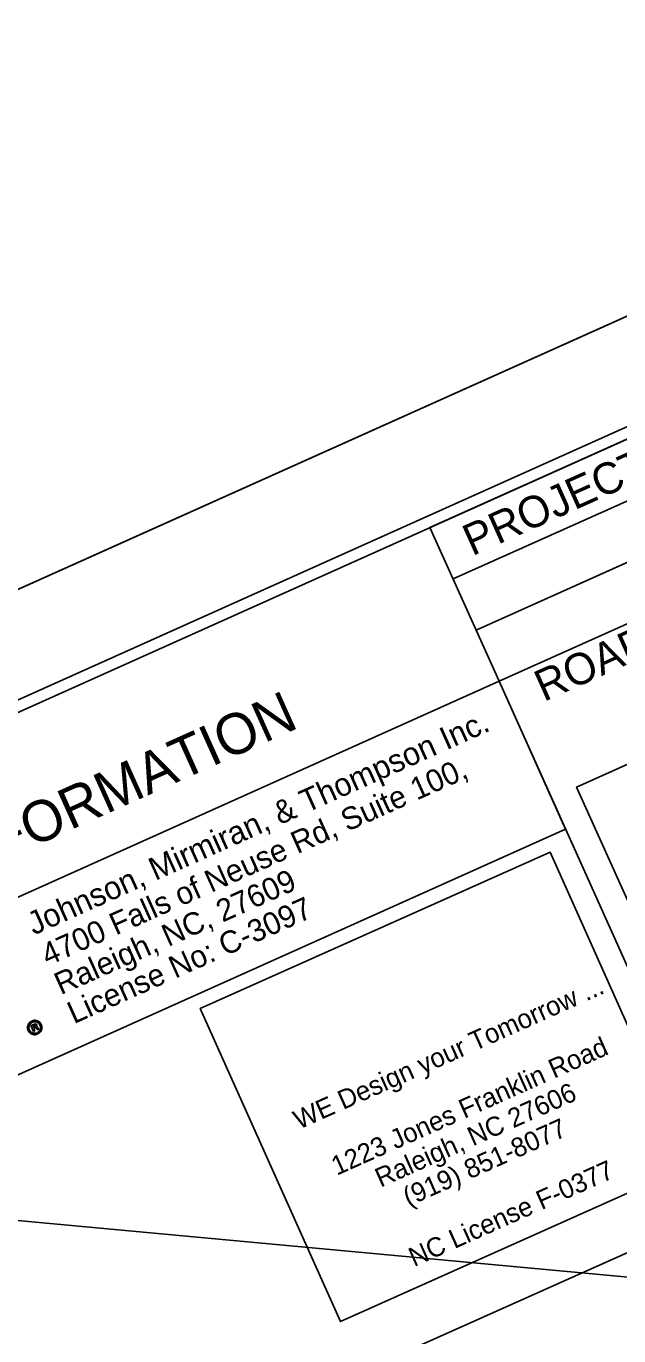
# Model space of a CAD drawing. Extents: x 553939 to 555925, y 502653 to 504347.
# Drawn here: x 555197.2 to 555329.1, y 504054.8 to 504346.6 of the extents above; entities that cross this region are included whole.
import ezdxf

# ---------------------------------------------------------------- set-up
doc = ezdxf.new("R2010")
doc.units = 0
for name, color, linetype in [('Matchline', 7, 'Continuous'), ('Prop DSN Text', 7, 'Continuous'), ('Prop Horizontal Alignment Curve and Spiral Data', 7, 'Continuous'), ('Sheet Border Standard 30in CELL', 7, 'Continuous'), ('Sheet Clip Boundary CELL', 7, 'Continuous'), ('Sheet Cutting Line CELL', 7, 'Continuous'), ('Sheet Plot Border Inside CELL', 7, 'Continuous'), ('Sheet Plot Border Outside CELL', 7, 'Continuous'), ('Sheet Sticker Incomplete CELL', 7, 'Continuous')]:
    doc.layers.add(name, color=color, linetype=linetype)

msp = doc.modelspace()

# ---------------------------------------------------------------- linework, layer by layer
at = {"layer": 'Matchline'}
for p, q in [((555198.29, 504123.93), (555198.82, 504124.17)), ((555198.88, 504122.63), (555198.29, 504123.93)), ((555198.48, 504124.94), (555198.6, 504124.67)), ((555198.6, 504124.67), (555198.48, 504124.94)), ((555198.93, 504123.92), (555198.7, 504123.82)), ((555198.7, 504123.82), (555198.84, 504123.51)), ((555198.82, 504124.17), (555198.91, 504124.21)), ((555198.82, 504124.17), (555198.93, 504123.92)), ((555198.93, 504123.92), (555198.82, 504124.17)), ((555198.84, 504123.51), (555199.07, 504123.62)), ((555198.97, 504123.94), (555198.93, 504123.92)), ((555199.18, 504123.38), (555198.94, 504123.27)), ((555198.94, 504123.27), (555199.17, 504122.76)), ((555199.07, 504123.62), (555199.18, 504123.38)), ((555199.18, 504123.38), (555199.07, 504123.62)), ((555199.07, 504123.62), (555199.09, 504123.62)), ((555199.19, 504123.38), (555199.18, 504123.38)), ((555199.17, 504122.76), (555198.88, 504122.63)), ((555199.64, 504122.36), (555199.77, 504122.07)), ((555199.77, 504122.07), (555199.64, 504122.36)), ((555199.64, 504122.36), (555199.65, 504122.36)), ((555199.78, 504122.08), (555199.77, 504122.07))]:
    msp.add_line(p, q, dxfattribs=at)
msp.add_lwpolyline([(555134.79, 504085.77), (555317.28, 504167.72), (555302.49, 504200.65), (555120.01, 504118.71)], close=True, dxfattribs=at)
msp.add_lwpolyline([(555199.84, 504123.43), (555199.87, 504123.36), (555199.91, 504123.32), (555199.93, 504123.27), (555200.03, 504123.15), (555199.75, 504123.02)], dxfattribs=at)
for points, degree in [([(555199.77, 504122.07), (555199.38, 504121.9), (555198.97, 504121.88), (555198.56, 504122.04), (555198.15, 504122.19), (555197.85, 504122.47), (555197.67, 504122.87), (555197.49, 504123.27), (555197.47, 504123.68), (555197.64, 504124.07), (555197.8, 504124.47), (555198.07, 504124.76), (555198.48, 504124.94)], 3), ([(555198.6, 504124.67), (555198.28, 504124.53), (555198.05, 504124.3), (555197.92, 504123.98), (555197.8, 504123.66), (555197.81, 504123.32), (555197.95, 504123), (555198.1, 504122.68), (555198.34, 504122.45), (555198.67, 504122.32), (555199, 504122.2), (555199.32, 504122.21), (555199.64, 504122.36)], 3), ([(555198.48, 504124.94), (555198.88, 504125.13), (555199.29, 504125.14), (555199.69, 504124.99), (555200.1, 504124.86), (555200.39, 504124.58), (555200.58, 504124.18)], 3), ([(555199.65, 504122.36), (555199.97, 504122.51), (555200.2, 504122.74), (555200.32, 504123.06), (555200.44, 504123.39), (555200.43, 504123.73), (555200.29, 504124.05), (555200.15, 504124.37), (555199.9, 504124.6), (555199.57, 504124.72), (555199.25, 504124.84), (555198.93, 504124.82), (555198.6, 504124.67)], 3), ([(555198.91, 504124.21), (555199.24, 504124.36), (555199.46, 504124.3), (555199.58, 504124.04), (555199.63, 504123.92), (555199.63, 504123.81), (555199.55, 504123.69)], 3), ([(555199.09, 504123.62), (555199.28, 504123.71), (555199.34, 504123.81), (555199.3, 504123.92), (555199.25, 504124.01), (555199.15, 504124.02), (555198.97, 504123.94)], 3), ([(555199.44, 504123.44), (555199.39, 504123.45), (555199.31, 504123.44), (555199.19, 504123.38)], 2), ([(555199.75, 504123.02), (555199.69, 504123.08), (555199.63, 504123.14), (555199.59, 504123.23), (555199.53, 504123.35), (555199.49, 504123.42), (555199.44, 504123.44)], 3), ([(555199.55, 504123.69), (555199.66, 504123.68), (555199.75, 504123.59), (555199.84, 504123.43)], 2), ([(555200.58, 504124.18), (555200.76, 504123.77), (555200.77, 504123.37), (555200.62, 504122.96), (555200.46, 504122.56), (555200.18, 504122.26), (555199.78, 504122.08)], 3)]:
    msp.add_open_spline(points, degree=degree, dxfattribs=at)
at = {"layer": 'Prop DSN Text'}
msp.add_lwpolyline([(555345.07, 504092.81), (555267.17, 504057.98), (555235.98, 504127.72), (555313.88, 504162.55)], close=True, dxfattribs=at)
at = {"layer": 'Prop Horizontal Alignment Curve and Spiral Data'}
msp.add_lwpolyline([(555073.67, 503958.23), (555091.71, 503918.08), (555365.32, 504040.41), (555347.29, 504080.56), (555073.67, 503958.23)], dxfattribs=at)
at = {"layer": 'Sheet Border Standard 30in CELL'}
for p, q in [((555292.25, 504223.45), (555474.75, 504305.4)), ((555297.37, 504212.05), (555479.87, 504294)), ((555297.37, 504212.05), (555479.87, 504294)), ((555297.37, 504212.05), (555302.49, 504200.65))]:
    msp.add_line(p, q, dxfattribs=at)
for points in [[(555469.6, 504316.85), (554101.23, 503702.4), (554531.34, 502744.54), (555899.72, 503358.98)], [(555287.11, 504234.9), (555469.6, 504316.85), (555479.87, 504294), (555297.37, 504212.05)], [(555302.49, 504200.65), (555393.76, 504241.63), (555439.84, 504139), (555348.57, 504098.02)]]:
    msp.add_lwpolyline(points, close=True, dxfattribs=at)
at = {"layer": 'Sheet Clip Boundary CELL'}
for points in [[(554122.43, 503695.68), (555128.42, 504154.2), (555095.7, 504120), (555113.65, 504088.12), (555364.03, 504064.84), (555538.05, 504147.98), (555542.54, 504077.37), (555561.42, 504000.98), (555608.35, 503927.62), (555814.87, 503478.7), (555868.57, 503357.36), (555699.98, 503280.3), (555640.99, 503255.83), (555512.69, 503541.56), (555029.44, 503324.56), (555157.75, 503038.83), (555094.66, 503015.3), (554759.27, 502917.8)], [(554122.43, 503695.68), (555128.42, 504154.2), (555095.7, 504120), (555113.65, 504088.12), (555364.03, 504064.84), (555538.05, 504147.98), (555542.54, 504077.37), (555561.42, 504000.98), (555610.11, 503951.13), (555644.95, 503906.87), (555662.42, 503867.97), (555642.54, 503853.07), (555814.87, 503478.7), (555868.57, 503357.36), (555699.98, 503280.3), (555640.99, 503255.83), (555512.69, 503541.56), (555029.44, 503324.56), (555157.75, 503038.83), (555094.66, 503015.3), (554864.55, 502951)]]:
    msp.add_lwpolyline(points, dxfattribs=at)
at = {"layer": 'Sheet Cutting Line CELL'}
msp.add_line((555474.87, 504346.62), (553938.64, 503656.8), dxfattribs=at)
at = {"layer": 'Sheet Plot Border Inside CELL'}
msp.add_lwpolyline([(555479.96, 504324.29), (553959.7, 503641.65), (554391.9, 502679.13), (555912.16, 503361.78)], close=True, dxfattribs=at)
at = {"layer": 'Sheet Plot Border Outside CELL'}
msp.add_lwpolyline([(555474.87, 504346.62), (553938.64, 503656.8), (554389.23, 502653.32), (555925.47, 503343.14)], close=True, dxfattribs=at)
at = {"layer": 'Sheet Sticker Incomplete CELL'}
msp.add_lwpolyline([(555331.81, 504150.28), (555319.77, 504177.08), (555487.4, 504252.35), (555499.43, 504225.55)], close=True, dxfattribs=at)

# ---------------------------------------------------------------- texts
at = {"layer": 'Matchline'}
for s, height, p in [('Johnson, Mirmiran, & Thompson Inc.', 5.1112, (555198.94, 504144.02)), ('4700 Falls of Neuse Rd, Suite 100, ', 4.9652, (555202.02, 504137.17)), ('Raleigh, NC, 27609', 4.9652, (555204.92, 504130.7)), ('License No: C-3097', 4.9652, (555207.83, 504124.23))]:
    msp.add_text(s, height=height, rotation=24.1816, dxfattribs=at).set_placement(p)
at = {"layer": 'Prop DSN Text'}
for s, p in [('WE Design your Tomorrow ...', (555257.95, 504100.73)), ('1223 Jones Franklin Road', (555266.36, 504090.47)), ('Raleigh, NC 27606', (555276.11, 504087.82)), ('(919) 851-8077', (555282.32, 504083.59)), ('NC License F-0377', (555283.58, 504070.13))]:
    msp.add_text(s, height=4.2667, rotation=24.0905, dxfattribs=at).set_placement(p)
at = {"layer": 'Prop Horizontal Alignment Curve and Spiral Data'}
msp.add_text('SEE SHEET 4A FOR R/W INFORMATION', height=9.1, rotation=24.1816, dxfattribs=at).set_placement((555047.27, 504095.7))
at = {"layer": 'Sheet Border Standard 30in CELL'}
for s, p in [('PROJECT REFERENCE NO.', (555296.5, 504228.49)), ('ROADWAY DESIGN', (555312.45, 504196.02))]:
    msp.add_text(s, height=7, rotation=24.1816, dxfattribs=at).set_placement(p)

doc.saveas('drawing.dxf')
